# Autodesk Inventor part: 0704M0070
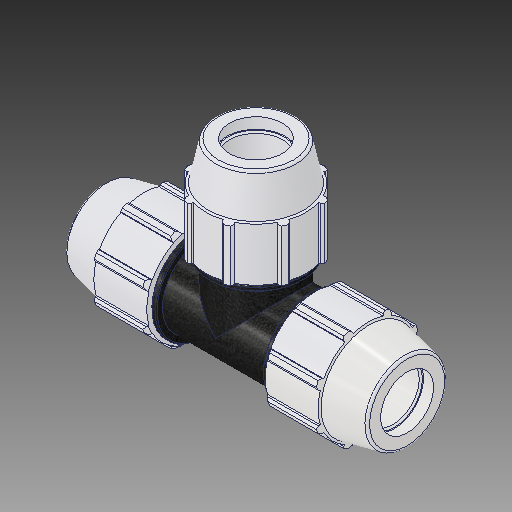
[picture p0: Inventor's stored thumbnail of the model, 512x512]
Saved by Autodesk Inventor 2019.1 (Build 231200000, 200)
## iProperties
Created: 2017-02
Part Number: 0704M0070
Material: PVC-Piping
Description: PLASSON TEE 3/4'' - 3/4'' - 3/4''
Document SubType Name: Modeling
Designer: KIM
Mass: 92.6774 g
Surface Area: 199.44 cm^2
Volume: 66.1981 cm^3
Density: 1.4 g/cm^3
Appearance: PTFE
Author: KIM
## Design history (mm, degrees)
derived "0704M0.ipt"
feature "Solid1::0704M0.ipt"
tag "TaggingFeature1"
body "Solid1"
other parameters: "d2" = 26.6, "d4" = 6.4135, "d5" = 19.2405, "d7" = 54.102, "d11" = 2.5654, "d13" = 120 deg, "d14" = 39.9, "d15" = 12 deg, "d16" = 47.06874, "d18" = 1.33, "d19" = 35 deg, "d20" = 17.5 deg, "d21" = 50.31486, "d23" = 0, "d25" = 360 deg, "d27" = 1.08204, "d33" = 0.532, "d42" = 26.9367, "d43" = 1.62306, "d46" = 0.798, "d63" = 56.896, "d67" = 40.5765, "d76" = 26.6, "d77" = 54.102, "d78" = 12 deg, "d79" = 76.962, "d80" = 120 deg, "d81" = 39.9, "d82" = 6.4135, "d85" = 40.5765, "d86" = 47.06874, "d87" = 2.5654, "d88" = 2.5654, "d89" = 19.2405, "d90" = 26.9367, "d96" = 7.6962, "d98" = 50.31486, "d99" = 35 deg, "d100" = 17.5 deg, "d102" = 0, "d103" = 1.08204, "d107" = 360 deg, "d109" = 0.798, "d112" = 1.33, "d118" = 360 deg, "d121" = 0, "d128" = 151.892, "d131" = 23.94, "d132" = 23.94, "d133" = 56.896, "d134" = 1.13792, "d135" = 7.6962, "d152" = 0, "d154" = 0, "d156" = 0, "d158" = 0, "d_" = 26.6, "E_" = 54.102, "A_" = 76.962, "l_" = 56.896, "H_" = 151.892
